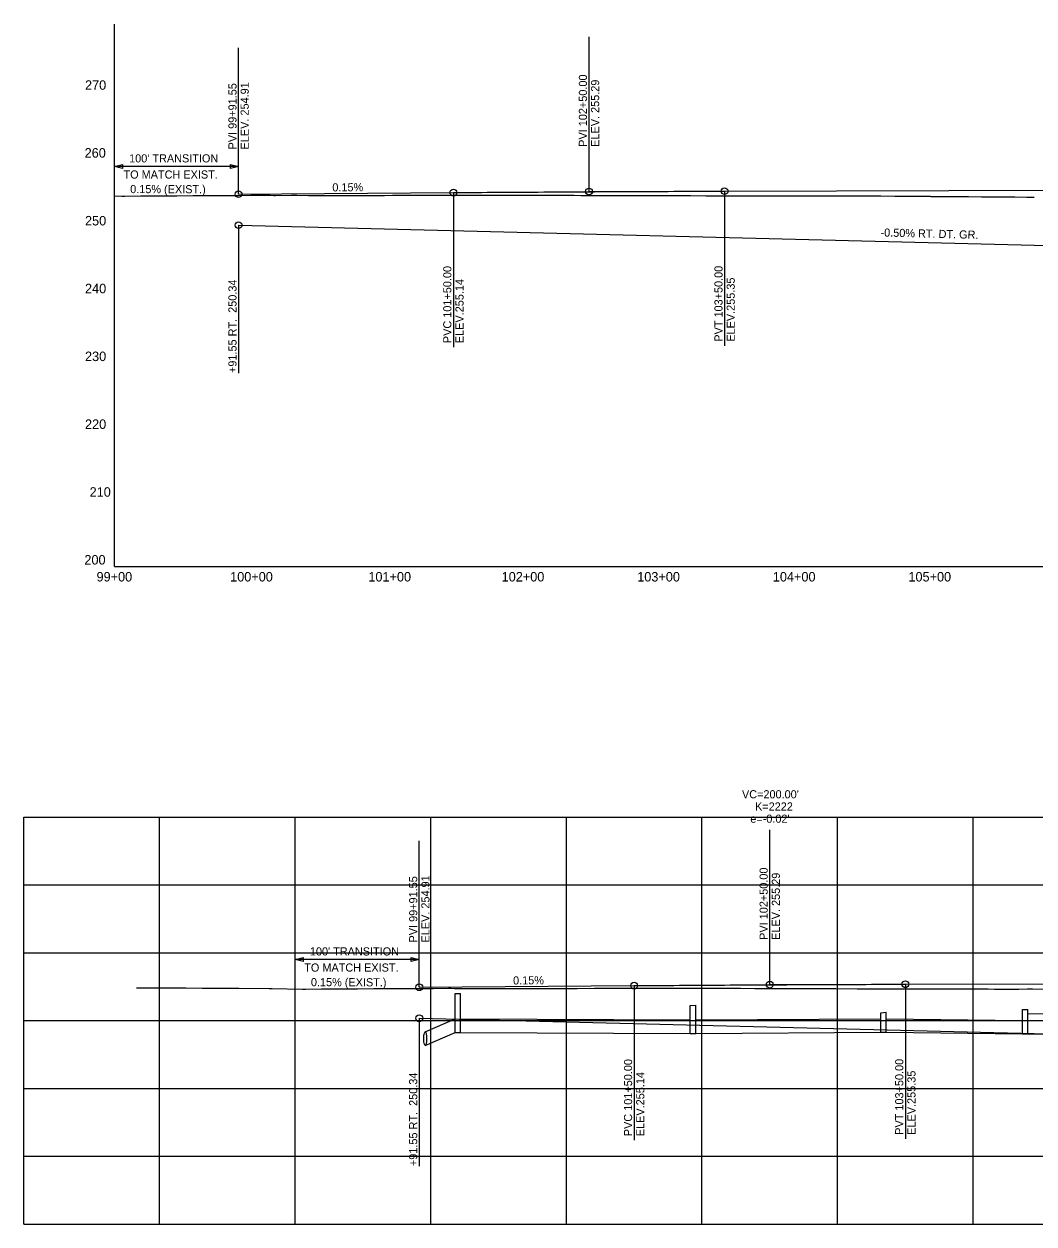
# Model space of a CAD drawing. Extents: x 1930770 to 1938778, y 596900 to 600561.
# Drawn here: x 1932093 to 1932838, y 598575 to 599459 of the extents above; entities that cross this region are included whole.
import ezdxf

# ---------------------------------------------------------------- set-up
doc = ezdxf.new("R2010")
doc.units = 0
for name, color, linetype in [('S_CROSS_DRAIN_ANNOT', 7, 'Continuous'), ('S_DROP_INLET_ANNOT', 7, 'Continuous'), ('S_ELECTRIC_UTILITIES_ANNOT', 7, 'Continuous'), ('S_HIST_HIGH_WATER_ANNOT', 7, 'Continuous'), ('S_SIGN_ANNOT', 7, 'Continuous'), ('S_STORM_SEWER_ANNOT', 7, 'Continuous'), ('S_UTILITY_POLE_ANNOT', 7, 'Continuous'), ('S_WATER_UTILITIES_ANNOT', 7, 'Continuous')]:
    doc.layers.add(name, color=color, linetype=linetype)

msp = doc.modelspace()

# ---------------------------------------------------------------- linework, layer by layer
at = {"layer": 'S_CROSS_DRAIN_ANNOT'}
for p, q in [((1932159.37, 599059.21), (1932159.37, 599459.21)), ((1932159.37, 599059.21), (1933659.37, 599059.21)), ((1932092.67, 598574.55), (1932092.67, 598874.55)), ((1932092.67, 598574.55), (1934792.67, 598574.55))]:
    msp.add_line(p, q, dxfattribs=at)
at = {"layer": 'S_ELECTRIC_UTILITIES_ANNOT'}
for p, q in [((1932509.37, 599365.69), (1932509.37, 599449.69)), ((1932250.92, 599363.75), (1932250.92, 599441.75)), ((1932509.37, 599335.69), (1932509.37, 599365.69)), ((1932250.92, 599333.75), (1932250.92, 599363.75)), ((1932409.37, 599334.94), (1932409.37, 599304.94)), ((1932459.37, 599335.31), (1932509.37, 599335.69)), ((1932509.37, 599335.69), (1932559.37, 599335.84)), ((1932609.37, 599335.99), (1932609.37, 599305.99)), ((1932250.92, 599310.91), (1932250.92, 599285.91)), ((1932409.37, 599304.94), (1932409.37, 599220.94)), ((1932609.37, 599305.99), (1932609.37, 599221.99)), ((1932250.92, 599285.91), (1932250.92, 599201.91)), ((1932642.67, 598781.03), (1932642.67, 598865.03)), ((1932384.22, 598779.09), (1932384.22, 598857.09)), ((1932384.22, 598749.09), (1932384.22, 598779.09)), ((1932642.67, 598751.03), (1932642.67, 598781.03)), ((1932542.67, 598750.28), (1932542.67, 598720.28)), ((1932592.67, 598750.65), (1932642.67, 598751.03)), ((1932642.67, 598751.03), (1932692.67, 598751.18)), ((1932742.67, 598751.33), (1932742.67, 598721.33)), ((1932384.22, 598726.25), (1932384.22, 598701.25)), ((1932542.67, 598720.28), (1932542.67, 598636.28)), ((1932742.67, 598721.33), (1932742.67, 598637.33)), ((1932384.22, 598701.25), (1932384.22, 598617.25))]:
    msp.add_line(p, q, dxfattribs=at)
for centre in [(1932250.92, 599333.75), (1932409.37, 599334.94), (1932509.37, 599335.69), (1932609.37, 599335.99), (1932384.22, 598749.09), (1932542.67, 598750.28), (1932642.67, 598751.03), (1932742.67, 598751.33)]:
    msp.add_circle(centre, 2.5, dxfattribs=at)
at = {"layer": 'S_HIST_HIGH_WATER_ANNOT'}
for p, q in [((1932250.92, 599333.75), (1932409.37, 599334.94)), ((1932609.37, 599335.99), (1933207.37, 599337.78)), ((1932250.92, 599310.91), (1933281.35, 599285.15)), ((1932384.22, 598749.09), (1932542.67, 598750.28)), ((1932742.67, 598751.33), (1933340.67, 598753.12)), ((1932384.22, 598726.25), (1933414.65, 598700.49))]:
    msp.add_line(p, q, dxfattribs=at)
for points in [[(1932409.37, 599334.94), (1932413.54, 599334.97), (1932417.71, 599335), (1932421.87, 599335.03), (1932426.04, 599335.06), (1932430.21, 599335.09), (1932434.37, 599335.12), (1932438.54, 599335.15), (1932442.71, 599335.18), (1932446.87, 599335.2), (1932451.04, 599335.23), (1932455.21, 599335.26), (1932459.37, 599335.28), (1932463.54, 599335.31), (1932467.71, 599335.34), (1932471.87, 599335.36), (1932476.04, 599335.39), (1932480.21, 599335.41), (1932484.37, 599335.44), (1932488.54, 599335.46), (1932492.71, 599335.48), (1932496.87, 599335.51), (1932501.04, 599335.53), (1932505.21, 599335.55), (1932513.54, 599335.6), (1932517.71, 599335.62), (1932521.87, 599335.64), (1932526.04, 599335.66), (1932530.21, 599335.68), (1932534.37, 599335.7), (1932538.54, 599335.72), (1932542.71, 599335.74), (1932546.87, 599335.76), (1932551.04, 599335.77), (1932555.21, 599335.79), (1932559.37, 599335.81), (1932563.54, 599335.83), (1932567.71, 599335.84), (1932571.87, 599335.86), (1932576.04, 599335.88), (1932580.21, 599335.89), (1932584.37, 599335.91), (1932588.54, 599335.92), (1932592.71, 599335.93), (1932596.87, 599335.95), (1932601.04, 599335.96), (1932605.21, 599335.98), (1932609.37, 599335.99)], [(1932542.67, 598750.28), (1932546.83, 598750.31), (1932551, 598750.34), (1932555.17, 598750.37), (1932559.33, 598750.4), (1932563.5, 598750.43), (1932567.67, 598750.46), (1932571.83, 598750.49), (1932576, 598750.52), (1932580.17, 598750.54), (1932584.33, 598750.57), (1932588.5, 598750.6), (1932592.67, 598750.63), (1932596.83, 598750.65), (1932601, 598750.68), (1932605.17, 598750.7), (1932609.33, 598750.73), (1932613.5, 598750.75), (1932617.67, 598750.78), (1932621.83, 598750.8), (1932626, 598750.83), (1932630.17, 598750.85), (1932634.33, 598750.87), (1932638.5, 598750.89), (1932646.83, 598750.94), (1932651, 598750.96), (1932655.17, 598750.98), (1932659.33, 598751), (1932663.5, 598751.02), (1932667.67, 598751.04), (1932671.83, 598751.06), (1932676, 598751.08), (1932680.17, 598751.1), (1932684.33, 598751.12), (1932688.5, 598751.13), (1932692.67, 598751.15), (1932696.83, 598751.17), (1932701, 598751.18), (1932705.17, 598751.2), (1932709.33, 598751.22), (1932713.5, 598751.23), (1932717.67, 598751.25), (1932721.83, 598751.26), (1932726, 598751.28), (1932730.17, 598751.29), (1932734.33, 598751.3), (1932738.5, 598751.32), (1932742.67, 598751.33)]]:
    msp.add_lwpolyline(points, dxfattribs=at)
for centre in [(1932250.92, 599310.91), (1932384.22, 598726.25)]:
    msp.add_circle(centre, 2.5, dxfattribs=at)
at = {"layer": 'S_SIGN_ANNOT'}
for p, q in [((1932410.67, 598715.8), (1932410.67, 598744.48)), ((1932410.67, 598744.48), (1932414.67, 598744.43)), ((1932414.67, 598715.8), (1932414.67, 598744.43)), ((1932584.09, 598735.55), (1932588.09, 598735.84)), ((1932584.09, 598715.1), (1932584.09, 598735.55)), ((1932588.09, 598715.1), (1932588.09, 598735.84)), ((1932724.56, 598730.31), (1932728.56, 598730.73)), ((1932724.56, 598715.9), (1932724.56, 598730.31)), ((1932728.56, 598715.9), (1932728.56, 598730.73)), ((1932828.98, 598732.68), (1932832.98, 598732.72)), ((1932828.98, 598714.7), (1932828.98, 598732.68)), ((1932832.98, 598714.7), (1932832.98, 598732.72)), ((1932832.98, 598729.7), (1932951.83, 598729.25)), ((1932388.59, 598716.15), (1932410.67, 598725.8)), ((1932414.67, 598725.8), (1932584.09, 598725.1)), ((1932588.09, 598725.1), (1932724.56, 598725.9)), ((1932728.56, 598725.9), (1932828.98, 598724.7)), ((1932388.59, 598706.15), (1932410.67, 598715.8)), ((1932410.67, 598715.8), (1932414.67, 598715.8)), ((1932414.67, 598715.8), (1932584.09, 598715.1)), ((1932584.09, 598715.1), (1932588.09, 598715.1)), ((1932588.09, 598715.1), (1932724.56, 598715.9)), ((1932724.56, 598715.9), (1932728.56, 598715.9)), ((1932728.56, 598715.9), (1932828.98, 598714.7)), ((1932828.98, 598714.7), (1932832.98, 598714.7)), ((1932832.98, 598714.7), (1932951.83, 598714.25))]:
    msp.add_line(p, q, dxfattribs=at)
msp.add_ellipse((1932388.59, 598711.15), major_axis=(0, 5), ratio=0.2, dxfattribs=at)
at = {"layer": 'S_STORM_SEWER_ANNOT'}
for p, q in [((1932159.37, 599333.71), (1932159.37, 599357.18)), ((1932250.92, 599333.71), (1932250.92, 599357.18)), ((1932250.92, 599354.18), (1932159.37, 599354.18)), ((1932292.67, 598749.05), (1932292.67, 598772.52)), ((1932384.22, 598769.52), (1932292.67, 598769.52)), ((1932384.22, 598749.05), (1932384.22, 598772.52))]:
    msp.add_line(p, q, dxfattribs=at)
for points in [[(1932165.37, 599352.68), (1932159.37, 599354.18), (1932165.37, 599355.68)], [(1932244.92, 599355.68), (1932250.92, 599354.18), (1932244.92, 599352.68)], [(1932298.67, 598768.02), (1932292.67, 598769.52), (1932298.67, 598771.02)], [(1932378.22, 598771.02), (1932384.22, 598769.52), (1932378.22, 598768.02)]]:
    msp.add_lwpolyline(points, close=True, dxfattribs=at)
at = {"layer": 'S_UTILITY_POLE_ANNOT'}
for p, q in [((1932092.67, 598874.55), (1934792.67, 598874.55)), ((1932092.67, 598874.55), (1934792.67, 598874.55)), ((1932192.67, 598574.55), (1932192.67, 598874.55)), ((1932292.67, 598574.55), (1932292.67, 598874.55)), ((1932392.67, 598574.55), (1932392.67, 598874.55)), ((1932492.67, 598574.55), (1932492.67, 598874.55)), ((1932592.67, 598574.55), (1932592.67, 598874.55)), ((1932692.67, 598574.55), (1932692.67, 598874.55)), ((1932792.67, 598574.55), (1932792.67, 598874.55)), ((1932092.67, 598824.55), (1934792.67, 598824.55)), ((1932092.67, 598774.55), (1934792.67, 598774.55)), ((1932092.67, 598724.55), (1934792.67, 598724.55)), ((1932092.67, 598674.55), (1934792.67, 598674.55)), ((1932092.67, 598624.55), (1934792.67, 598624.55))]:
    msp.add_line(p, q, dxfattribs=at)
at = {"layer": 'S_WATER_UTILITIES_ANNOT'}
for points in [[(1932159.37, 599332.47), (1932164.83, 599332.4), (1932165.92, 599332.39), (1932166.99, 599332.39), (1932178.78, 599332.47), (1932179.8, 599332.48), (1932191.64, 599332.55), (1932192.61, 599332.56), (1932204.5, 599332.64), (1932205.42, 599332.64), (1932217.36, 599332.72), (1932218.34, 599332.72), (1932231.58, 599332.79), (1932232.6, 599332.79), (1932245.81, 599332.85), (1932246.85, 599332.85), (1932250.92, 599332.87), (1932260.03, 599332.92), (1932261.12, 599332.92), (1932272.46, 599332.98), (1932274.26, 599332.98), (1932276.92, 599332.89), (1932277.2, 599332.89), (1932277.42, 599332.89), (1932278.22, 599332.89), (1932290.01, 599332.92), (1932290.9, 599332.92), (1932293.99, 599332.91), (1932302.54, 599332.9), (1932303.5, 599332.89), (1932315.07, 599332.88), (1932315.53, 599332.88), (1932316.11, 599332.87), (1932327.59, 599332.85), (1932328.74, 599332.84), (1932337.06, 599332.83), (1932340.11, 599332.83), (1932342.6, 599332.83), (1932358.59, 599332.9), (1932364.49, 599332.92), (1932367.38, 599332.93), (1932380.13, 599332.97), (1932388.87, 599333), (1932390.63, 599333.01), (1932401.63, 599333.04), (1932401.66, 599333.04), (1932403.51, 599333.04), (1932414.38, 599333.07), (1932416.42, 599333.08), (1932423.19, 599333.09), (1932427.14, 599333.1), (1932429.35, 599333.11), (1932439.9, 599333.13), (1932444.73, 599333.12), (1932456.96, 599333.07), (1932461.05, 599333.06), (1932466.26, 599333.04), (1932477.68, 599333), (1932482.21, 599332.98), (1932487.8, 599332.96), (1932498.33, 599332.92), (1932503.36, 599332.9), (1932509.33, 599332.87), (1932518.9, 599332.83), (1932524.52, 599332.81), (1932530.86, 599332.8), (1932531.65, 599332.8), (1932549.28, 599332.75), (1932552.4, 599332.75), (1932558.1, 599332.74), (1932573.93, 599332.69), (1932573.99, 599332.69), (1932584.14, 599332.67), (1932595.46, 599332.64), (1932597.3, 599332.63), (1932609.37, 599332.59), (1932617, 599332.58), (1932620.66, 599332.57), (1932627.08, 599332.54), (1932634.28, 599332.54), (1932638.53, 599332.52), (1932640.14, 599332.51), (1932647.9, 599332.51), (1932656.31, 599332.5), (1932660.06, 599332.48), (1932661.5, 599332.48), (1932670.54, 599332.47), (1932675.09, 599332.45), (1932681.6, 599332.45), (1932693.12, 599332.44), (1932699.49, 599332.46), (1932703.13, 599332.46), (1932719.54, 599332.44), (1932723.88, 599332.46), (1932724.67, 599332.45), (1932734.81, 599332.37), (1932736.4, 599332.35), (1932746.2, 599332.28), (1932747.92, 599332.27), (1932748.93, 599332.26), (1932761.05, 599332.17), (1932761.45, 599332.16), (1932767.73, 599332.11), (1932769.6, 599332.1), (1932773.96, 599332.05), (1932775.07, 599332.05), (1932789.27, 599331.93), (1932798.74, 599331.85), (1932806.85, 599331.82), (1932810.8, 599331.79), (1932823.55, 599331.7), (1932832.33, 599331.63), (1932837.63, 599331.6)], [(1932175.56, 598748.65), (1932177.84, 598748.64), (1932179.65, 598748.65), (1932198.22, 598748.63), (1932199.18, 598748.62), (1932211.14, 598748.57), (1932212.14, 598748.56), (1932224.07, 598748.51), (1932225.1, 598748.51), (1932236.99, 598748.46), (1932238.06, 598748.45), (1932249.91, 598748.4), (1932251.03, 598748.39), (1932273.46, 598748.07), (1932274.57, 598748.06), (1932275.66, 598748.06), (1932298.13, 598747.74), (1932299.22, 598747.73), (1932300.28, 598747.73), (1932312.08, 598747.81), (1932313.1, 598747.82), (1932324.94, 598747.9), (1932325.91, 598747.9), (1932337.8, 598747.98), (1932338.72, 598747.98), (1932350.66, 598748.06), (1932351.64, 598748.06), (1932364.88, 598748.13), (1932365.89, 598748.13), (1932379.1, 598748.2), (1932380.15, 598748.19), (1932384.22, 598748.22), (1932393.33, 598748.26), (1932394.41, 598748.26), (1932405.75, 598748.32), (1932407.55, 598748.32), (1932410.21, 598748.23), (1932410.5, 598748.23), (1932410.72, 598748.23), (1932411.52, 598748.23), (1932423.31, 598748.26), (1932424.2, 598748.26), (1932427.29, 598748.25), (1932435.84, 598748.24), (1932436.8, 598748.24), (1932448.36, 598748.22), (1932448.82, 598748.22), (1932449.41, 598748.21), (1932460.89, 598748.19), (1932462.03, 598748.19), (1932470.36, 598748.17), (1932473.41, 598748.17), (1932475.9, 598748.17), (1932491.89, 598748.24), (1932497.78, 598748.26), (1932500.67, 598748.27), (1932513.42, 598748.31), (1932522.17, 598748.34), (1932523.93, 598748.35), (1932534.92, 598748.38), (1932534.96, 598748.38), (1932536.81, 598748.38), (1932547.68, 598748.41), (1932549.72, 598748.42), (1932556.49, 598748.43), (1932560.44, 598748.44), (1932562.64, 598748.45), (1932573.2, 598748.47), (1932578.02, 598748.46), (1932590.25, 598748.41), (1932594.35, 598748.4), (1932599.56, 598748.38), (1932610.98, 598748.34), (1932615.5, 598748.32), (1932621.09, 598748.3), (1932631.63, 598748.26), (1932636.66, 598748.24), (1932642.62, 598748.22), (1932652.2, 598748.17), (1932657.81, 598748.15), (1932664.16, 598748.14), (1932664.94, 598748.14), (1932682.57, 598748.1), (1932685.69, 598748.09), (1932691.39, 598748.08), (1932707.23, 598748.03), (1932707.28, 598748.03), (1932717.43, 598748.02), (1932728.76, 598747.98), (1932730.6, 598747.97), (1932742.67, 598747.93), (1932750.29, 598747.92), (1932753.96, 598747.91), (1932760.38, 598747.88), (1932767.58, 598747.88), (1932771.83, 598747.86), (1932773.44, 598747.85), (1932781.19, 598747.85), (1932789.6, 598747.84), (1932793.36, 598747.82), (1932794.79, 598747.82), (1932803.84, 598747.81), (1932808.38, 598747.79), (1932814.89, 598747.79), (1932826.42, 598747.78), (1932832.78, 598747.81), (1932836.43, 598747.8), (1932852.83, 598747.78)]]:
    msp.add_lwpolyline(points, dxfattribs=at)

# ---------------------------------------------------------------- texts
at = {"layer": 'S_DROP_INLET_ANNOT'}
for s, p in [('270', (1932137.68, 599410.71)), ('260', (1932137.4, 599360.71)), ('250', (1932137.68, 599310.71)), ('240', (1932137.68, 599260.71)), ('230', (1932137.68, 599210.71)), ('220', (1932137.68, 599160.71)), ('210', (1932141.08, 599110.71)), ('200', (1932137.21, 599060.71)), ('99+00', (1932146.17, 599048.21)), ('100+00', (1932244.7, 599048.21)), ('101+00', (1932346.64, 599048.21)), ('102+00', (1932444.94, 599048.21)), ('103+00', (1932544.94, 599048.21)), ('104+00', (1932644.94, 599048.21)), ('105+00', (1932744.94, 599048.21))]:
    msp.add_text(s, height=7, dxfattribs=at).set_placement(p)
at = {"layer": 'S_ELECTRIC_UTILITIES_ANNOT'}
for s, rotation, p in [('PVI 102+50.00', 90, (1932507.87, 599368.69)), ('PVI 99+91.55', 90, (1932249.42, 599366.75)), ('ELEV. 254.91', 90, (1932258.42, 599366.75)), ('ELEV. 255.29', 90, (1932516.87, 599368.69)), ('0.15% (EXIST.)', 359.84683, (1932170.98, 599334.53)), ('0.15%', 0.42971, (1932320.1, 599335.77)), ('-0.50% RT. DT. GR.', 358.5679, (1932724.33, 599302.58)), ('PVC 101+50.00', 90, (1932407.87, 599223.94)), ('PVT 103+50.00', 90, (1932607.87, 599224.99)), ('+91.55 RT.  250.34', 90, (1932249.42, 599201.91)), ('ELEV.255.14', 90, (1932416.87, 599223.94)), ('ELEV.255.35', 90, (1932616.87, 599224.99)), ('PVI 102+50.00', 90, (1932641.17, 598784.03)), ('PVI 99+91.55', 90, (1932382.72, 598782.09)), ('ELEV. 254.91', 90, (1932391.72, 598782.09)), ('ELEV. 255.29', 90, (1932650.17, 598784.03)), ('0.15% (EXIST.)', 359.84683, (1932304.27, 598749.87)), ('0.15%', 0.42971, (1932453.39, 598751.11)), ('PVC 101+50.00', 90, (1932541.17, 598639.28)), ('PVT 103+50.00', 90, (1932741.17, 598640.33)), ('+91.55 RT.  250.34', 90, (1932382.72, 598617.25)), ('ELEV.255.14', 90, (1932550.17, 598639.28)), ('ELEV.255.35', 90, (1932750.17, 598640.33))]:
    msp.add_text(s, height=6, rotation=rotation, dxfattribs=at).set_placement(p)
for s, p in [("VC=200.00'", (1932622.19, 598888.36)), ('K=2222', (1932631.83, 598879.36)), ("e=-0.02'", (1932628.33, 598870.36))]:
    msp.add_text(s, height=6, dxfattribs=at).set_placement(p)
at = {"layer": 'S_STORM_SEWER_ANNOT'}
for s, p in [("100' TRANSITION", (1932170.21, 599357.16)), ('TO MATCH EXIST.', (1932166.07, 599345.26)), ("100' TRANSITION", (1932303.51, 598772.5)), ('TO MATCH EXIST.', (1932299.37, 598760.6))]:
    msp.add_text(s, height=6, rotation=0.00482, dxfattribs=at).set_placement(p)
msp.add_text('-', height=0.0001, dxfattribs=at).set_placement((1932159.37, 599059.21))

doc.saveas('drawing.dxf')
